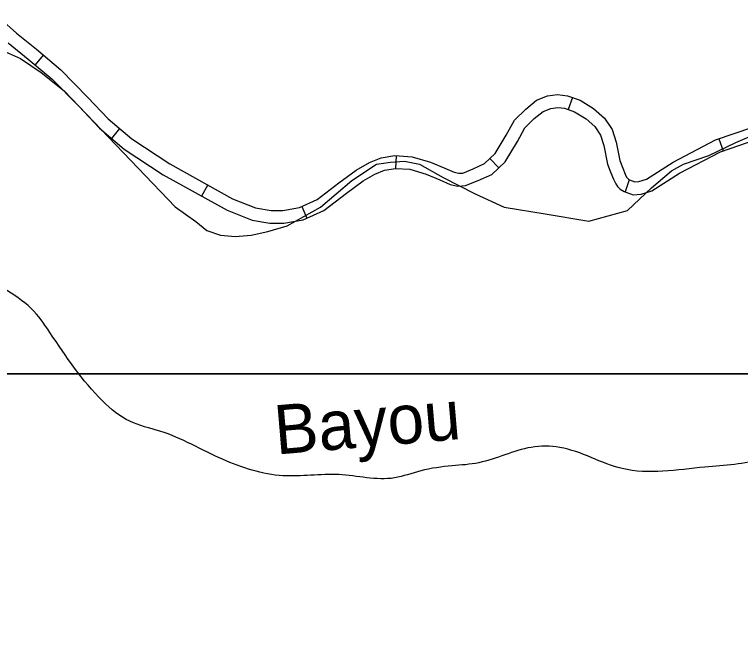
# Model space of a CAD drawing. Extents: x 3192986 to 3230865, y 867483 to 892886.
# Drawn here: x 3218165 to 3219876, y 881777 to 883257 of the extents above; entities that cross this region are included whole.
import ezdxf

# ---------------------------------------------------------------- set-up
doc = ezdxf.new("R2010")
doc.units = 0
for name, color, linetype in [('V-RIVR-IDEN', 7, 'Continuous'), ('V-ROAD-CNTR', 7, 'Continuous'), ('V-SITE-VEGE', 7, 'Continuous'), ('V-TOPO-SHOR', 7, 'Continuous')]:
    doc.layers.add(name, color=color, linetype=linetype)

msp = doc.modelspace()

# ---------------------------------------------------------------- linework, layer by layer
at = {"layer": 'V-ROAD-CNTR'}
for p, q in [((3218232.6, 883161.5), (3218213.2, 883138.6)), ((3219479.7, 883061.6), (3219469.5, 883033.4)), ((3218412.3, 882988.4), (3218392.9, 882965.5)), ((3219824.7, 882964.5), (3219834.4, 882936.1)), ((3219064.5, 882924.4), (3219062.8, 882894.5)), ((3219285.2, 882917.7), (3219305.7, 882895.7)), ((3218620, 882855.8), (3218605.5, 882829.5)), ((3219613.3, 882867.6), (3219603.5, 882839.2)), ((3218841.6, 882804.6), (3218853.8, 882777.2))]:
    msp.add_line(p, q, dxfattribs=at)
for points in [[(3218132.5, 883246.8), (3218169.4, 883213.1), (3218216.2, 883175.4), (3218273.7, 883126.7), (3218337.6, 883061.8), (3218385.5, 883011.2), (3218441, 882964), (3218530.9, 882905.2), (3218678.6, 882823.2), (3218732.9, 882801.9), (3218769.3, 882795.7), (3218797.2, 882795.7), (3218836.3, 882802.2), (3218878.2, 882820.9), (3218929.1, 882860.5), (3218969.7, 882890.7), (3219001, 882908.4), (3219028.6, 882919.2), (3219060.8, 882924.7), (3219101.8, 882922.2), (3219145.2, 882909.3), (3219179, 882895.4), (3219200.6, 882885.5), (3219211.9, 882883.2), (3219221.3, 882883.6), (3219245.4, 882893.7), (3219272.6, 882905.9), (3219297.8, 882929.4), (3219323.7, 882972.6), (3219343.2, 883008.7), (3219369.4, 883034.5), (3219395.1, 883055.3), (3219420.9, 883065.5), (3219444.7, 883068.6), (3219467.6, 883066), (3219497.6, 883055.2), (3219529.4, 883035.9), (3219554.9, 883013.1), (3219572.8, 882986.4), (3219582.4, 882956.7), (3219591.4, 882913.3), (3219598.2, 882894.9), (3219603.5, 882881.2), (3219607.2, 882873.9), (3219609.2, 882871.2), (3219611.3, 882868.9), (3219614, 882867.3), (3219626.6, 882863), (3219635.7, 882863.8), (3219653.7, 882869.3), (3219716.7, 882909.1), (3219816.5, 882961.6), (3219904.5, 882991.9)], [(3218149.8, 883190.3), (3218197.1, 883152.3), (3218253.3, 883104.7), (3218316, 883041), (3218364.9, 882989.3), (3218423, 882939.9), (3218515.4, 882879.5), (3218665.8, 882796.1), (3218724.8, 882772.8), (3218766.7, 882765.7), (3218799.7, 882765.7), (3218845, 882773.3), (3218893.7, 882795), (3218947.2, 882836.6), (3218986.1, 882865.5), (3219013.9, 882881.2), (3219036.7, 882890.1), (3219062.5, 882894.5), (3219096.6, 882892.5), (3219135.2, 882881), (3219167, 882867.9), (3219191.2, 882856.8), (3219209.6, 882853), (3219227.9, 882853.9), (3219257.3, 882866.2), (3219289.4, 882880.5), (3219321.3, 882910.3), (3219349.7, 882957.7), (3219367.5, 882990.5), (3219389.4, 883012.1), (3219410.4, 883029.1), (3219428.5, 883036.2), (3219445, 883038.4), (3219460.7, 883036.6), (3219484.6, 883028), (3219511.5, 883011.7), (3219532.1, 882993.3), (3219545.5, 882973.2), (3219553.4, 882949), (3219562.5, 882904.9), (3219570.2, 882884.3), (3219576.1, 882868.9), (3219581.6, 882858.3), (3219585.9, 882852.3), (3219592.1, 882845.4), (3219601.4, 882839.9), (3219622.9, 882832.5), (3219641.5, 882834.2), (3219666.3, 882841.7), (3219731.7, 882883.1), (3219828.4, 882934), (3219915.2, 882963.8)], [(3218128.6, 883175.9), (3218178.5, 883154), (3218227.4, 883121), (3218281.4, 883077.5), (3218543.1, 882804.1), (3218591.8, 882769.7), (3218618.2, 882747.8), (3218650.3, 882737.5), (3218684.4, 882734), (3218722.6, 882736.8), (3218761.3, 882746.2), (3218807.3, 882759.1), (3218886.1, 882803.4), (3218959.8, 882866.1), (3219017.9, 882904.5), (3219050.5, 882909.7), (3219083.4, 882911.8), (3219119.4, 882904.9), (3219174.7, 882873.1), (3219250.1, 882834.9), (3219318.9, 882803.1), (3219415.4, 882787.6), (3219518.5, 882770.5), (3219609.3, 882795.5), (3219665.6, 882848.5), (3219713.2, 882889.1), (3219741.6, 882904.3), (3219801.3, 882925.1), (3219864.8, 882955.9), (3219943, 882989.2)]]:
    msp.add_lwpolyline(points, dxfattribs=at)
at = {"layer": 'V-SITE-VEGE'}
msp.add_line((3215293.8, 882410.3), (3223237.7, 882410.3), dxfattribs=at)
msp.add_lwpolyline([(3223237.7, 882410.3), (3215293.8, 882410.3)], dxfattribs=at)
at = {"layer": 'V-TOPO-SHOR'}
msp.add_spline([(3220607.9, 883199.2), (3220556.6, 882928.6), (3220515.7, 882851.2), (3220465.6, 882706.2), (3220430.9, 882570.1), (3220379.2, 882505.8), (3220271.9, 882419.1), (3220211.6, 882387.8), (3220155.9, 882347.3), (3220040.6, 882280.2), (3219987.2, 882238.8), (3219928.3, 882210.2), (3219791.8, 882190.3), (3219596.9, 882186.8), (3219449.9, 882236.7), (3219382.4, 882236.9), (3219259.1, 882200.6), (3219196.3, 882193.2), (3219122.1, 882181.5), (3219060, 882164.8), (3218928.8, 882172.5), (3218797.4, 882170), (3218655, 882208.7), (3218507.4, 882275), (3218436.3, 882298.3), (3218372.7, 882345.8), (3218248.1, 882507.7), (3218204, 882564.3), (3218139.8, 882611.1), (3218066.6, 882648.9), (3218002.7, 882654), (3217945.7, 882626.2), (3217854.1, 882485.8), (3217751.1, 882382.9), (3217706.7, 882304.3), (3217684.4, 882231.9), (3217658.8, 882027.8), (3217607.4, 881968.1), (3217545.8, 881963.9), (3217403, 881998.1), (3217345.4, 881975), (3217238.8, 881893.4), (3217179.3, 881868.5), (3217112.2, 881868.3), (3216902.2, 881905.6), (3216773.3, 881906.4), (3216626.2, 881977), (3216554.8, 882004.2), (3216487.5, 882014.3), (3216412, 882043.2), (3216346.8, 882045.6), (3216319, 882038.1), (3216297.4, 882015.2), (3216166.6, 882007.7), (3216039.6, 881975.8), (3215985, 881942.7), (3215950.8, 881866.5), (3215944.2, 881801.5), (3215938, 881733.2), (3215887.7, 881682.8), (3215768.7, 881641.4), (3215640.8, 881623.2), (3215558.6, 881662.6), (3215466.9, 881717.1), (3215359.5, 881762.4), (3215352.6, 881880.7), (3215338.7, 881992), (3215296.9, 882158.9), (3215310.8, 882249.4), (3215296.9, 882339.8), (3215331.7, 882409.4), (3215394.3, 882534.6), (3215429.1, 882687.6), (3215456.9, 882785), (3215436.1, 882840.7), (3215429.1, 882896.3), (3215430, 882941.3), (3215392.3, 882993.6), (3215270.5, 883089.5), (3215204.8, 883100.5), (3215141.6, 883148.3), (3215155.2, 883215), (3215200, 883290.4), (3215187.9, 883417.1), (3215237.3, 883490.8), (3215287.5, 883538.3), (3215287.7, 883538.5)], degree=3, dxfattribs=at)

# ---------------------------------------------------------------- texts
at = {"layer": 'V-RIVR-IDEN'}
msp.add_text('Bayou', height=116, rotation=4.8439, dxfattribs=at).set_placement((3218781.5, 882219.7))

doc.saveas('drawing.dxf')
